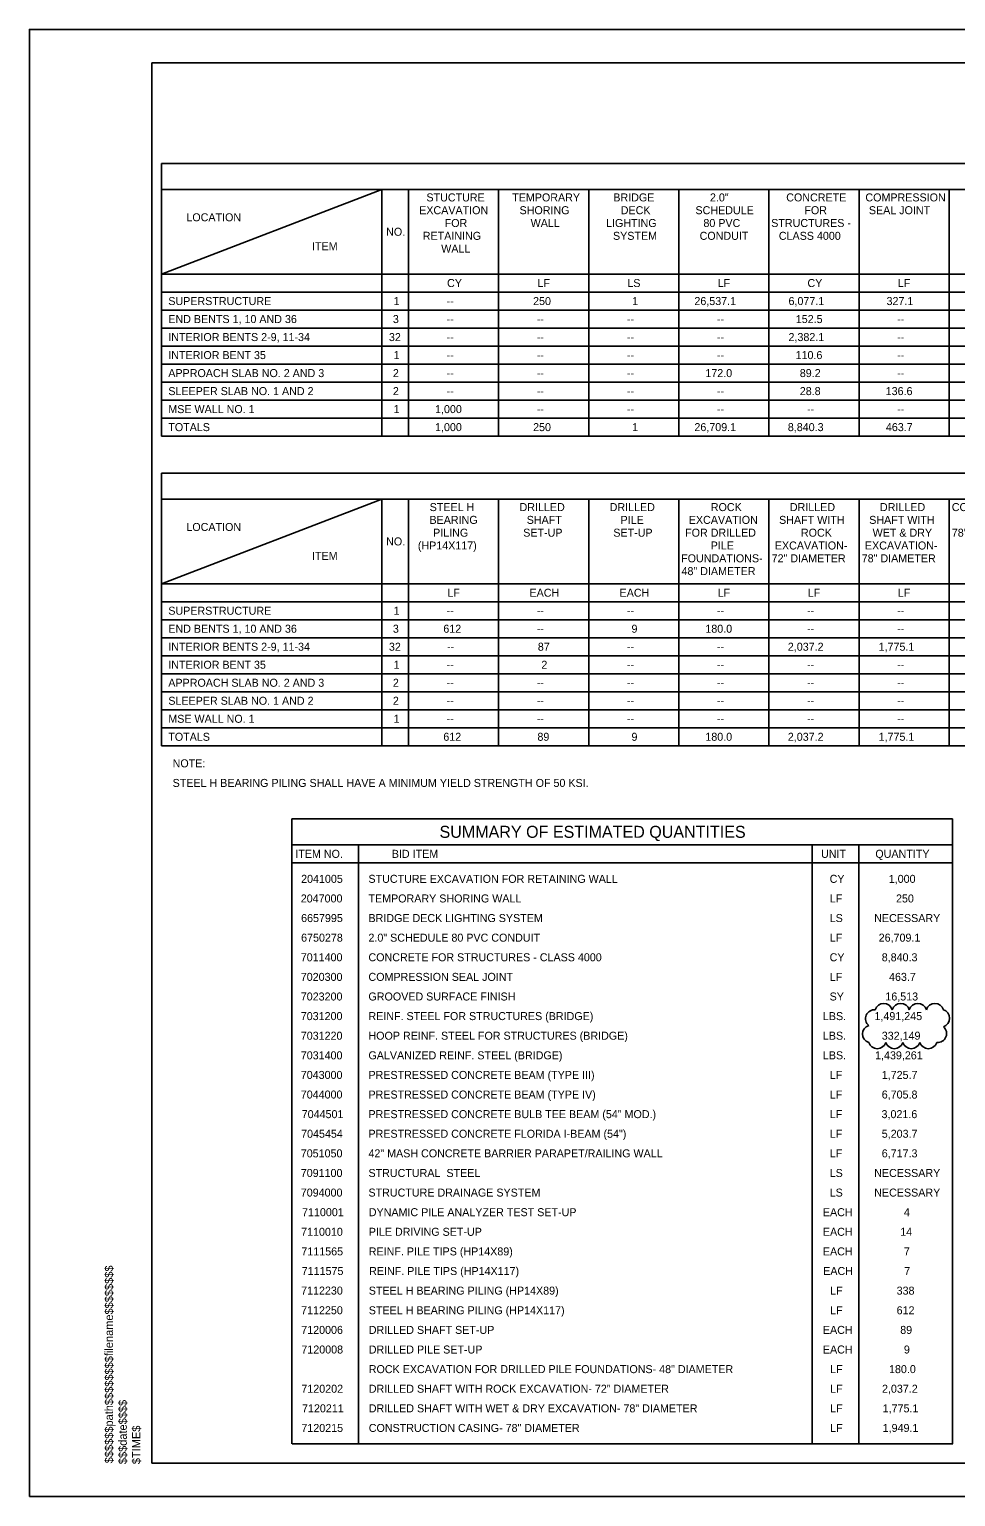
# Model space of a CAD drawing. Extents: x -125.5 to -89.4, y -5.1 to 16.9.
# Drawn here: x -125.53 to -111.65, y -5.07 to 16.93 of the extents above; entities that cross this region are included whole.
import ezdxf

# ---------------------------------------------------------------- set-up
doc = ezdxf.new("R2010")
doc.units = 0
for name, color, linetype in [('BR_BORDER LINES', 7, 'Continuous'), ('BR_TABLE LINES', 7, 'Continuous'), ('BR_TEXT', 7, 'Continuous'), ('Level 31', 7, 'Continuous'), ('RD_SHT_ID', 7, 'Continuous')]:
    doc.layers.add(name, color=color, linetype=linetype)

msp = doc.modelspace()

# ---------------------------------------------------------------- linework, layer by layer
at = {"layer": 'BR_BORDER LINES'}
for p, q in [((-90.033, 16.434), (-123.699, 16.434)), ((-123.699, -4.566), (-123.699, 16.434)), ((-123.699, -4.566), (-90.033, -4.566))]:
    msp.add_line(p, q, dxfattribs=at)
at = {"layer": 'BR_TABLE LINES'}
for p, q in [((-123.551, 14.923), (-90.138, 14.923)), ((-123.551, 14.923), (-123.551, 10.835)), ((-123.551, 14.533), (-90.138, 14.533)), ((-123.551, 13.265), (-120.251, 14.533)), ((-120.251, 14.533), (-120.251, 10.835)), ((-119.851, 14.533), (-119.851, 10.835)), ((-118.501, 14.533), (-118.501, 10.835)), ((-117.151, 14.533), (-117.151, 10.835)), ((-115.801, 14.533), (-115.801, 10.835)), ((-114.451, 14.533), (-114.451, 10.835)), ((-113.101, 14.533), (-113.101, 10.835)), ((-111.751, 14.533), (-111.751, 10.835)), ((-123.551, 13.265), (-90.138, 13.265)), ((-123.551, 12.995), (-90.138, 12.995)), ((-90.138, 12.725), (-123.551, 12.725)), ((-90.138, 12.455), (-123.551, 12.455)), ((-90.138, 12.185), (-123.551, 12.185)), ((-90.138, 11.915), (-123.551, 11.915)), ((-90.138, 11.645), (-123.551, 11.645)), ((-90.138, 11.375), (-123.551, 11.375)), ((-90.138, 11.105), (-123.551, 11.105)), ((-90.138, 10.835), (-123.551, 10.835)), ((-123.551, 10.28), (-91.389, 10.28)), ((-123.551, 10.28), (-123.551, 6.192)), ((-123.551, 9.89), (-91.389, 9.89)), ((-123.551, 8.622), (-120.251, 9.89)), ((-120.251, 9.89), (-120.251, 6.192)), ((-119.851, 9.89), (-119.851, 6.192)), ((-118.501, 9.89), (-118.501, 6.192)), ((-117.151, 9.89), (-117.151, 6.192)), ((-115.801, 9.89), (-115.801, 6.192)), ((-114.451, 9.89), (-114.451, 6.192)), ((-113.101, 9.89), (-113.101, 6.192)), ((-111.751, 9.89), (-111.751, 6.192)), ((-123.551, 8.622), (-91.389, 8.622)), ((-123.551, 8.352), (-91.389, 8.352)), ((-91.389, 8.082), (-123.551, 8.082)), ((-91.389, 7.812), (-123.551, 7.812)), ((-91.389, 7.542), (-123.551, 7.542)), ((-91.389, 7.272), (-123.551, 7.272)), ((-91.389, 7.002), (-123.551, 7.002)), ((-91.389, 6.732), (-123.551, 6.732)), ((-91.389, 6.462), (-123.551, 6.462)), ((-91.389, 6.192), (-123.551, 6.192)), ((-121.602, -4.275), (-121.602, 5.097)), ((-121.602, 5.097), (-111.702, 5.097)), ((-111.702, -4.275), (-111.702, 5.097)), ((-121.602, 4.707), (-111.702, 4.707)), ((-120.602, -4.275), (-120.602, 4.707)), ((-113.802, -4.275), (-113.802, 4.707)), ((-113.102, -4.275), (-113.102, 4.707)), ((-121.602, 4.437), (-111.702, 4.437)), ((-121.597, -4.275), (-111.697, -4.275))]:
    msp.add_line(p, q, dxfattribs=at)
at = {"layer": 'BR_TEXT'}
for centre, start, end in [((-112.87, 2.101), 85.0572, 230.0572), ((-112.731, 2.194), 17.5, 162.5), ((-112.476, 2.194), 17.5, 162.5), ((-112.22, 2.194), 17.5, 162.5), ((-111.965, 2.194), 17.5, 162.5), ((-111.878, 2.107), 287.5, 72.5), ((-112.915, 1.871), 107.5, 252.5), ((-111.923, 1.877), 265.0572, 50.0572), ((-112.828, 1.784), 197.5, 342.5), ((-112.573, 1.784), 197.5, 342.5), ((-112.318, 1.784), 197.5, 342.5), ((-112.063, 1.784), 197.5, 342.5)]:
    msp.add_arc(centre, 0.134, start, end, dxfattribs=at)
at = {"layer": 'Level 31'}
msp.add_lwpolyline([(-125.533, -5.066), (-89.533, -5.066), (-89.533, 16.934), (-125.533, 16.934)], close=True, dxfattribs=at)

# ---------------------------------------------------------------- texts
at = {"layer": 'BR_TEXT'}
for s, height, p in [('STUCTURE ', 0.12, (-119.583, 14.354)), ('TEMPORARY ', 0.12, (-118.298, 14.354)), ('BRIDGE ', 0.12, (-116.783, 14.354)), ('2.0"', 0.12, (-115.335, 14.354)), ('CONCRETE ', 0.12, (-114.192, 14.354)), ('COMPRESSION ', 0.12, (-113.006, 14.354)), ('LOCATION', 0.12, (-123.18, 14.056)), ('EXCAVATION ', 0.12, (-119.692, 14.162)), ('FOR ', 0.12, (-119.31, 13.97)), ('SHORING ', 0.12, (-118.188, 14.162)), ('WALL', 0.12, (-118.022, 13.97)), ('LIGHTING ', 0.12, (-116.892, 13.97)), ('DECK ', 0.12, (-116.672, 14.162)), (' SCHEDULE', 0.12, (-115.597, 14.162)), ('80 PVC ', 0.12, (-115.433, 13.97)), ('STRUCTURES - ', 0.12, (-114.417, 13.97)), ('FOR ', 0.12, (-113.92, 14.162)), ('SEAL JOINT', 0.12, (-112.954, 14.162)), ('NO.', 0.12, (-120.187, 13.839)), ('RETAINING ', 0.12, (-119.638, 13.778)), ('SYSTEM', 0.12, (-116.788, 13.778)), ('CONDUIT', 0.12, (-115.49, 13.778)), ('CLASS 4000', 0.12, (-114.303, 13.778)), ('ITEM', 0.12, (-121.297, 13.622)), ('WALL', 0.12, (-119.362, 13.586)), ('CY', 0.12, (-119.274, 13.07)), ('LF', 0.12, (-117.92, 13.07)), ('LS', 0.12, (-116.573, 13.07)), ('LF', 0.12, (-115.22, 13.07)), ('CY', 0.12, (-113.874, 13.07)), ('LF', 0.12, (-112.52, 13.07)), ('SUPERSTRUCTURE', 0.12, (-123.451, 12.8)), ('1', 0.12, (-120.076, 12.8)), ('--', 0.12, (-119.28, 12.8)), ('250', 0.12, (-117.985, 12.8)), ('1', 0.12, (-116.501, 12.8)), ('26,537.1', 0.12, (-115.568, 12.8)), ('6,077.1', 0.12, (-114.158, 12.8)), ('327.1', 0.12, (-112.689, 12.8)), ('END BENTS 1, 10 AND 36', 0.12, (-123.451, 12.53)), ('3', 0.12, (-120.086, 12.53)), ('--', 0.12, (-119.28, 12.53)), ('--', 0.12, (-117.93, 12.53)), ('--', 0.12, (-116.58, 12.53)), ('--', 0.12, (-115.23, 12.53)), ('152.5', 0.12, (-114.049, 12.53)), ('--', 0.12, (-112.53, 12.53)), ('INTERIOR BENTS 2-9, 11-34', 0.12, (-123.451, 12.26)), ('32', 0.12, (-120.145, 12.26)), ('2,382.1', 0.12, (-114.158, 12.26)), ('INTERIOR BENT 35', 0.12, (-123.451, 11.99)), ('1', 0.12, (-120.076, 11.99)), ('--', 0.12, (-119.28, 12.26)), ('--', 0.12, (-117.93, 12.26)), ('--', 0.12, (-116.58, 12.26)), ('--', 0.12, (-115.23, 12.26)), ('110.6', 0.12, (-114.052, 11.99)), ('--', 0.12, (-112.53, 12.26)), ('--', 0.12, (-119.28, 11.99)), ('--', 0.12, (-117.93, 11.99)), ('--', 0.12, (-116.58, 11.99)), ('--', 0.12, (-115.23, 11.99)), ('--', 0.12, (-112.53, 11.99)), ('APPROACH SLAB NO. 2 AND 3', 0.12, (-123.451, 11.72)), ('2', 0.12, (-120.086, 11.72)), ('--', 0.12, (-119.28, 11.72)), ('--', 0.12, (-117.93, 11.72)), ('--', 0.12, (-116.58, 11.72)), ('172.0', 0.12, (-115.404, 11.72)), ('89.2', 0.12, (-113.989, 11.72)), ('--', 0.12, (-112.53, 11.72)), ('SLEEPER SLAB NO. 1 AND 2', 0.12, (-123.451, 11.45)), ('2', 0.12, (-120.086, 11.45)), ('--', 0.12, (-119.28, 11.45)), ('--', 0.12, (-117.93, 11.45)), ('--', 0.12, (-116.58, 11.45)), ('--', 0.12, (-115.23, 11.45)), ('28.8', 0.12, (-113.989, 11.45)), ('136.6', 0.12, (-112.702, 11.45)), ('MSE WALL NO. 1', 0.12, (-123.451, 11.18)), ('1', 0.12, (-120.076, 11.18)), ('1,000', 0.12, (-119.454, 11.18)), ('--', 0.12, (-117.93, 11.18)), ('--', 0.12, (-116.58, 11.18)), ('--', 0.12, (-115.23, 11.18)), ('--', 0.12, (-113.88, 11.18)), ('--', 0.12, (-112.53, 11.18)), ('TOTALS', 0.12, (-123.451, 10.91)), ('1,000', 0.12, (-119.454, 10.91)), ('250', 0.12, (-117.985, 10.91)), ('1', 0.12, (-116.501, 10.91)), ('26,709.1', 0.12, (-115.568, 10.91)), ('8,840.3', 0.12, (-114.168, 10.91)), ('463.7', 0.12, (-112.699, 10.91)), ('STEEL H ', 0.12, (-119.535, 9.711)), ('DRILLED ', 0.12, (-118.188, 9.711)), ('DRILLED ', 0.12, (-116.838, 9.711)), ('ROCK ', 0.12, (-115.322, 9.711)), ('DRILLED ', 0.12, (-114.138, 9.711)), ('DRILLED ', 0.12, (-112.788, 9.711)), ('CONSTRUCTION ', 0.12, (-111.711, 9.711)), ('LOCATION', 0.12, (-123.18, 9.413)), ('BEARING ', 0.12, (-119.538, 9.519)), ('SHAFT ', 0.12, (-118.081, 9.519)), ('PILE ', 0.12, (-116.674, 9.519)), ('EXCAVATION ', 0.12, (-115.652, 9.519)), ('SHAFT WITH ', 0.12, (-114.299, 9.519)), ('SHAFT WITH ', 0.12, (-112.949, 9.519)), ('NO.', 0.12, (-120.187, 9.196)), ('(HP14X117)', 0.12, (-119.712, 9.135)), ('PILING ', 0.12, (-119.483, 9.327)), ('SET-UP', 0.12, (-118.133, 9.327)), ('SET-UP', 0.12, (-116.783, 9.327)), ('FOR DRILLED ', 0.12, (-115.707, 9.327)), ('PILE ', 0.12, (-115.324, 9.135)), ('EXCAVATION- ', 0.12, (-114.363, 9.135)), ('ROCK ', 0.12, (-113.972, 9.327)), ('EXCAVATION- ', 0.12, (-113.013, 9.135)), ('WET & DRY ', 0.12, (-112.898, 9.327)), ('78" DIAMETER', 0.12, (-111.711, 9.327)), ('ITEM', 0.12, (-121.297, 8.979)), ('FOUNDATIONS- ', 0.12, (-115.767, 8.943)), ('72" DIAMETER', 0.12, (-114.411, 8.943)), ('78" DIAMETER', 0.12, (-113.061, 8.943)), ('48" DIAMETER', 0.12, (-115.761, 8.751)), ('LF', 0.12, (-119.27, 8.427)), ('EACH', 0.12, (-118.039, 8.427)), ('EACH', 0.12, (-116.689, 8.427)), ('LF', 0.12, (-115.22, 8.427)), ('LF', 0.12, (-113.87, 8.427)), ('LF', 0.12, (-112.52, 8.427)), ('SUPERSTRUCTURE', 0.12, (-123.451, 8.157)), ('1', 0.12, (-120.076, 8.157)), ('--', 0.12, (-119.28, 8.157)), ('--', 0.12, (-117.93, 8.157)), ('--', 0.12, (-116.58, 8.157)), ('--', 0.12, (-115.23, 8.157)), ('--', 0.12, (-113.88, 8.157)), ('--', 0.12, (-112.53, 8.157)), ('END BENTS 1, 10 AND 36', 0.12, (-123.451, 7.887)), ('3', 0.12, (-120.086, 7.887)), ('612', 0.12, (-119.33, 7.887)), ('--', 0.12, (-117.93, 7.887)), ('9', 0.12, (-116.511, 7.887)), ('180.0', 0.12, (-115.404, 7.887)), ('--', 0.12, (-113.88, 7.887)), ('--', 0.12, (-112.53, 7.887)), ('INTERIOR BENTS 2-9, 11-34', 0.12, (-123.451, 7.617)), ('32', 0.12, (-120.145, 7.617)), ('87', 0.12, (-117.914, 7.617)), ('2,037.2', 0.12, (-114.168, 7.617)), ('1,775.1', 0.12, (-112.808, 7.617)), ('--', 0.12, (-119.274, 7.617)), ('--', 0.12, (-116.58, 7.617)), ('--', 0.12, (-115.23, 7.617)), ('INTERIOR BENT 35', 0.12, (-123.451, 7.347)), ('1', 0.12, (-120.076, 7.347)), ('--', 0.12, (-119.28, 7.347)), ('2', 0.12, (-117.861, 7.347)), ('--', 0.12, (-116.58, 7.347)), ('--', 0.12, (-115.23, 7.347)), ('--', 0.12, (-113.88, 7.347)), ('--', 0.12, (-112.53, 7.347)), ('APPROACH SLAB NO. 2 AND 3', 0.12, (-123.451, 7.077)), ('2', 0.12, (-120.086, 7.077)), ('--', 0.12, (-119.28, 7.077)), ('--', 0.12, (-117.93, 7.077)), ('--', 0.12, (-116.58, 7.077)), ('--', 0.12, (-115.23, 7.077)), ('--', 0.12, (-113.88, 7.077)), ('--', 0.12, (-112.53, 7.077)), ('SLEEPER SLAB NO. 1 AND 2', 0.12, (-123.451, 6.807)), ('2', 0.12, (-120.086, 6.807)), ('--', 0.12, (-119.28, 6.807)), ('--', 0.12, (-117.93, 6.807)), ('--', 0.12, (-116.58, 6.807)), ('--', 0.12, (-115.23, 6.807)), ('--', 0.12, (-113.88, 6.807)), ('--', 0.12, (-112.53, 6.807)), ('MSE WALL NO. 1', 0.12, (-123.451, 6.537)), ('1', 0.12, (-120.076, 6.537)), ('TOTALS', 0.12, (-123.451, 6.267)), ('612', 0.12, (-119.33, 6.267)), ('--', 0.12, (-119.28, 6.537)), ('--', 0.12, (-117.93, 6.537)), ('89', 0.12, (-117.92, 6.267)), ('--', 0.12, (-116.58, 6.537)), ('9', 0.12, (-116.511, 6.267)), ('180.0', 0.12, (-115.404, 6.267)), ('--', 0.12, (-115.23, 6.537)), ('2,037.2', 0.12, (-114.168, 6.267)), ('--', 0.12, (-113.88, 6.537)), ('1,775.1', 0.12, (-112.808, 6.267)), ('--', 0.12, (-112.53, 6.537)), ('NOTE:', 0.12, (-123.386, 5.869)), ('STEEL H BEARING PILING SHALL HAVE A MINIMUM YIELD STRENGTH OF 50 KSI. ', 0.12, (-123.386, 5.575)), ('SUMMARY OF ESTIMATED QUANTITIES', 0.18, (-119.387, 4.812)), ('ITEM NO.', 0.12, (-121.548, 4.512)), ('BID ITEM', 0.12, (-120.102, 4.512)), ('UNIT', 0.12, (-113.671, 4.512)), ('QUANTITY', 0.12, (-112.857, 4.512)), ('2041005', 0.12, (-121.461, 4.137)), ('STUCTURE EXCAVATION FOR RETAINING WALL', 0.12, (-120.452, 4.137)), ('CY', 0.12, (-113.542, 4.137)), ('1,000', 0.12, (-112.656, 4.137)), ('2047000', 0.12, (-121.466, 3.843)), ('TEMPORARY SHORING WALL', 0.12, (-120.452, 3.843)), ('LF', 0.12, (-113.538, 3.843)), ('250', 0.12, (-112.547, 3.843)), ('6657995', 0.12, (-121.461, 3.549)), ('BRIDGE DECK LIGHTING SYSTEM', 0.12, (-120.452, 3.549)), ('LS', 0.12, (-113.541, 3.549)), ('NECESSARY', 0.12, (-112.874, 3.549)), ('6750278', 0.12, (-121.461, 3.255)), ('2.0" SCHEDULE 80 PVC CONDUIT', 0.12, (-120.452, 3.255)), ('LF', 0.12, (-113.538, 3.255)), ('26,709.1', 0.12, (-112.807, 3.255)), ('7011400', 0.12, (-121.466, 2.961)), ('CONCRETE FOR STRUCTURES - CLASS 4000', 0.12, (-120.452, 2.961)), ('CY', 0.12, (-113.542, 2.961)), ('8,840.3', 0.12, (-112.761, 2.961)), ('7020300', 0.12, (-121.466, 2.667)), ('COMPRESSION SEAL JOINT', 0.12, (-120.452, 2.667)), ('LF', 0.12, (-113.538, 2.667)), ('463.7', 0.12, (-112.652, 2.667)), ('7023200', 0.12, (-121.466, 2.373)), ('GROOVED SURFACE FINISH', 0.12, (-120.452, 2.373)), ('SY', 0.12, (-113.542, 2.373)), ('16,513', 0.12, (-112.707, 2.373)), ('7031200', 0.12, (-121.466, 2.079)), ('REINF. STEEL FOR STRUCTURES (BRIDGE)', 0.12, (-120.452, 2.079)), ('LBS.', 0.12, (-113.643, 2.079)), ('1,491,245', 0.12, (-112.87, 2.079)), ('7031220', 0.12, (-121.466, 1.785)), ('HOOP REINF. STEEL FOR STRUCTURES (BRIDGE)', 0.12, (-120.452, 1.785)), ('LBS.', 0.12, (-113.643, 1.785)), ('332,149', 0.12, (-112.761, 1.785)), ('7031400', 0.12, (-121.466, 1.491)), ('GALVANIZED REINF. STEEL (BRIDGE)', 0.12, (-120.452, 1.491)), ('LBS.', 0.12, (-113.643, 1.491)), ('1,439,261', 0.12, (-112.861, 1.491)), ('PRESTRESSED CONCRETE BEAM (TYPE III)', 0.12, (-120.452, 1.197)), ('7043000', 0.12, (-121.466, 1.197)), ('LF', 0.12, (-113.538, 1.197)), ('1,725.7', 0.12, (-112.761, 1.197)), ('7044000', 0.12, (-121.466, 0.903)), ('PRESTRESSED CONCRETE BEAM (TYPE IV)', 0.12, (-120.452, 0.903)), ('LF', 0.12, (-113.538, 0.903)), ('6,705.8', 0.12, (-112.761, 0.903)), ('7044501', 0.12, (-121.452, 0.609)), ('PRESTRESSED CONCRETE BULB TEE BEAM (54" MOD.)', 0.12, (-120.452, 0.609)), ('LF', 0.12, (-113.538, 0.609)), ('3,021.6', 0.12, (-112.764, 0.609)), ('PRESTRESSED CONCRETE FLORIDA I-BEAM (54")', 0.12, (-120.452, 0.315)), ('7045454', 0.12, (-121.461, 0.315)), ('LF', 0.12, (-113.538, 0.315)), ('5,203.7', 0.12, (-112.761, 0.315)), ('7051050', 0.12, (-121.466, 0.021)), ('42" MASH CONCRETE BARRIER PARAPET/RAILING WALL', 0.12, (-120.452, 0.021)), ('LF', 0.12, (-113.538, 0.021)), ('6,717.3', 0.12, (-112.761, 0.021)), ('7091100', 0.12, (-121.466, -0.273)), ('STRUCTURAL  STEEL', 0.12, (-120.452, -0.273)), ('LS', 0.12, (-113.541, -0.273)), ('NECESSARY', 0.12, (-112.874, -0.273)), ('7094000', 0.12, (-121.466, -0.567)), ('STRUCTURE DRAINAGE SYSTEM', 0.12, (-120.452, -0.567)), ('LS', 0.12, (-113.541, -0.567)), ('NECESSARY', 0.12, (-112.874, -0.567)), ('7110001', 0.12, (-121.447, -0.861)), ('DYNAMIC PILE ANALYZER TEST SET-UP', 0.12, (-120.447, -0.861)), ('EACH', 0.12, (-113.643, -0.861)), ('4', 0.12, (-112.429, -0.861)), ('7110010', 0.12, (-121.461, -1.155)), ('PILE DRIVING SET-UP', 0.12, (-120.447, -1.155)), ('EACH', 0.12, (-113.643, -1.155)), ('14', 0.12, (-112.484, -1.155)), ('7111565', 0.12, (-121.457, -1.449)), ('REINF. PILE TIPS (HP14X89)', 0.12, (-120.447, -1.449)), ('EACH', 0.12, (-113.643, -1.449)), ('7', 0.12, (-112.429, -1.449)), ('7111575', 0.12, (-121.452, -1.743)), ('REINF. PILE TIPS (HP14X117)', 0.12, (-120.442, -1.743)), ('EACH', 0.12, (-113.638, -1.743)), ('7', 0.12, (-112.424, -1.743)), ('7112230', 0.12, (-121.461, -2.036)), ('STEEL H BEARING PILING (HP14X89)', 0.12, (-120.447, -2.037)), ('LF', 0.12, (-113.534, -2.037)), ('338', 0.12, (-112.538, -2.037)), ('7112250', 0.12, (-121.461, -2.331)), ('STEEL H BEARING PILING (HP14X117)', 0.12, (-120.447, -2.332)), ('LF', 0.12, (-113.534, -2.332)), ('612', 0.12, (-112.538, -2.332)), ('7120006', 0.12, (-121.459, -2.626)), ('DRILLED SHAFT SET-UP', 0.12, (-120.447, -2.626)), ('EACH', 0.12, (-113.643, -2.626)), ('89', 0.12, (-112.484, -2.626)), ('7120008', 0.12, (-121.457, -2.92)), ('DRILLED PILE SET-UP', 0.12, (-120.447, -2.92)), ('EACH', 0.12, (-113.643, -2.92)), ('9', 0.12, (-112.429, -2.92)), ('ROCK EXCAVATION FOR DRILLED PILE FOUNDATIONS- 48" DIAMETER', 0.12, (-120.447, -3.214)), ('LF', 0.12, (-113.534, -3.214)), ('180.0', 0.12, (-112.652, -3.214)), ('7120202', 0.12, (-121.457, -3.508)), ('DRILLED SHAFT WITH ROCK EXCAVATION- 72" DIAMETER', 0.12, (-120.447, -3.508)), ('LF', 0.12, (-113.534, -3.508)), ('2,037.2', 0.12, (-112.757, -3.508)), ('7120211', 0.12, (-121.447, -3.802)), ('DRILLED SHAFT WITH WET & DRY EXCAVATION- 78" DIAMETER', 0.12, (-120.447, -3.802)), ('LF', 0.12, (-113.534, -3.802)), ('1,775.1', 0.12, (-112.747, -3.802)), ('7120215', 0.12, (-121.457, -4.096)), ('CONSTRUCTION CASING- 78" DIAMETER', 0.12, (-120.447, -4.096)), ('LF', 0.12, (-113.534, -4.096)), ('1,949.1', 0.12, (-112.747, -4.096))]:
    msp.add_text(s, height=height, dxfattribs=at).set_placement(p)
at = {"layer": 'RD_SHT_ID'}
for s, height, p in [('$$$$$$path$$$$$$$$filename$$$$$$$$', 0.12347, (-124.279, -4.566)), ('$$$date$$$$', 0.12347, (-124.073, -4.579)), ('$TIME$', 0.1235, (-123.869, -4.579))]:
    msp.add_text(s, height=height, rotation=90, dxfattribs=at).set_placement(p)

doc.saveas('drawing.dxf')
